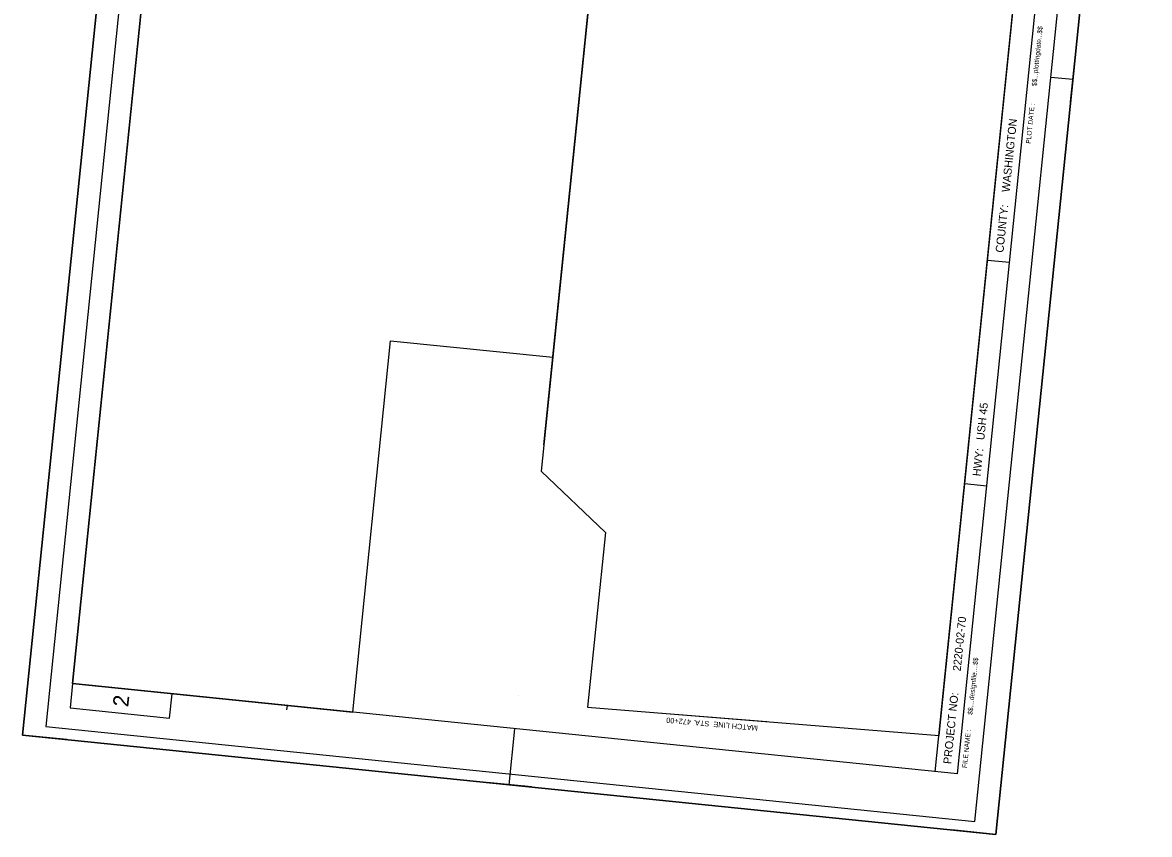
# Model space of a CAD drawing. Extents: x 359453 to 360720, y 169866 to 171669.
# Drawn here: x 359453 to 360720, y 169866 to 170778 of the extents above; entities that cross this region are included whole.
import ezdxf

# ---------------------------------------------------------------- set-up
doc = ezdxf.new("R2010")
doc.units = 0
for name, color, linetype in [('CA-MTCH-LINE', 7, 'Continuous'), ('CA-MTCH-LINE-TEXT', 7, 'Continuous'), ('Default', 7, 'Continuous'), ('P_Kapur_PFFE CELL [KAPUR_CADDS_LEVELS]', 7, 'Continuous'), ('P_RDWY_Text', 7, 'Continuous'), ('PLT_Sheet_Border', 7, 'Continuous'), ('PLT_Sheet_Info', 7, 'Continuous')]:
    doc.layers.add(name, color=color, linetype=linetype)

msp = doc.modelspace()

# ---------------------------------------------------------------- linework, layer by layer
at = {"layer": 'CA-MTCH-LINE'}
msp.add_line((360158.3, 170003), (360290.2, 169992.4), dxfattribs=at)
at = {"layer": 'Default'}
for points in [[(359509.5, 170035.2), (359824.6, 170003.1), (359867.1, 170420.4), (360049.6, 170401.8), (360049.6, 170401.8), (360164, 171523), (359665.5, 171563.1)], [(359509.5, 170035.2), (359824.6, 170003.1), (359867.1, 170420.4), (360049.6, 170401.8), (360164, 171523), (359665.5, 171563.1)], [(359509.5, 170035.2), (359824.6, 170003.1), (359867.1, 170420.4), (360049.6, 170401.8), (360164, 171523), (359665.5, 171563.1)], [(360049.6, 170401.8), (360036.5, 170273.7), (360108.9, 170205), (360088.7, 170008.7), (360483.7, 169976.8), (360636, 171469.2), (360162.4, 171507.3)], [(360049.6, 170401.8), (360036.5, 170273.7), (360108.9, 170205), (360088.7, 170008.7), (360483.7, 169976.8), (360636, 171469.2), (360162.4, 171507.3)], [(360049.6, 170401.8), (360036.5, 170273.7), (360108.9, 170205), (360088.7, 170008.7), (360483.7, 169976.8), (360636, 171469.2), (360162.4, 171507.3)]]:
    msp.add_lwpolyline(points, close=True, dxfattribs=at)
at = {"layer": 'P_Kapur_PFFE CELL [KAPUR_CADDS_LEVELS]'}
msp.add_lwpolyline([(359453.4, 169977.4), (359626, 171668.6), (360720.3, 171556.9), (360547.7, 169865.7), (359453.4, 169977.4)], dxfattribs=at)
at = {"layer": 'P_RDWY_Text'}
msp.add_lwpolyline([(359453.4, 169977.4), (359626, 171668.6), (360720.3, 171556.9), (360547.7, 169865.7)], close=True, dxfattribs=at)
at = {"layer": 'PLT_Sheet_Border'}
for points in [[(360547.7, 169865.7), (360720.3, 171556.9), (359626, 171668.6), (359453.4, 169977.4)], [(360524, 169880.2), (360692.1, 171526.6), (359647.5, 171633.2), (359479.5, 169986.8)]]:
    msp.add_lwpolyline(points, close=True, dxfattribs=at)
at = {"layer": 'PLT_Sheet_Info'}
for p, q in [((359509.5, 170035.2), (359669.5, 171602.1)), ((360039.5, 170303.6), (360166.9, 171551.3)), ((360479.5, 169936.2), (360639.4, 171503.1)), ((360504.4, 169933.7), (360664.3, 171500.5)), ((360631.7, 170688.9), (360636.8, 170738.6)), ((360634.3, 170713.8), (360609.4, 170716.3)), ((360563, 170508.2), (360538.1, 170510.7)), ((360537.4, 170257), (360512.5, 170259.5)), ((360504.4, 169933.7), (359509.5, 170035.2)), ((359453.4, 169977.4), (359458.5, 170027.1)), ((360010.8, 170021.8), (360010.8, 170021.8)), ((359750.8, 170010.6), (359750.3, 170005.6)), ((360000.5, 169921.5), (360007, 169984.4)), ((359503.1, 169972.3), (359453.4, 169977.4)), ((360025.4, 169919), (359975.7, 169924.1)), ((360547.7, 169865.7), (360552.8, 169915.4)), ((360547.7, 169865.7), (360498, 169870.8))]:
    msp.add_line(p, q, dxfattribs=at)
msp.add_lwpolyline([(359509.5, 170035.2), (359506.8, 170007.9), (359618.7, 169996.4), (359621.5, 170023.8)], close=True, dxfattribs=at)

# ---------------------------------------------------------------- texts
at = {"layer": 'CA-MTCH-LINE-TEXT'}
msp.add_text('MATCH LINE  STA. 472+00', height=6, rotation=174.9815, dxfattribs=at).set_placement((360280.3, 169988.1))
at = {"layer": 'PLT_Sheet_Info'}
for s, height, p in [('$$...plottingdate...$$', 5.4, (360593.3, 170706.2)), ('PLOT DATE :', 5.4, (360586.7, 170641.5)), (' WASHINGTON', 9, (360562.7, 170583.6)), ('COUNTY:', 9, (360556.1, 170519)), (' USH 45', 9, (360534.2, 170305.1)), ('HWY:', 9, (360530.4, 170267.8)), (' 2220-02-70', 9, (360507.7, 170045.4)), ('$$....designfile....$$', 5.4, (360521.2, 169999.8)), ('2', 17.5, (359572.2, 170008.4)), ('PROJECT NO:', 9, (360497.4, 169944.4)), ('FILE NAME :', 5.4, (360515.1, 169940.1))]:
    msp.add_text(s, height=height, rotation=84.1728, dxfattribs=at).set_placement(p)

doc.saveas('drawing.dxf')
